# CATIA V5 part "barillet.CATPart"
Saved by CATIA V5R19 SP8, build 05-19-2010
Part number: barillet
Bounding box of the stored display mesh (mm): x -92.5 to 142.5, y -182.368 to 182.368, z -182.368 to 182.368
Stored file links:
  U:\Rendu_cfao_elguidj\barillet.CATPart
  U:\Rendu_cfao_elguidj\squelettecouronne.CATPart
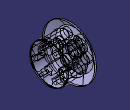
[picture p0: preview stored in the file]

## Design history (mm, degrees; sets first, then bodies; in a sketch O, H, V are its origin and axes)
Body1 (main body)
  DatumPoint1
  DatumCurve1
  Sketch1 on zx-plane, origin (0, 0, 0), H (-1, 0, 0), V (0, 0, 1)
    construction line L1 (114.6366, 0) -> (-102.6747, 0)
    point P1 (114.6366, 0)
    point P3 (-142.5, 128.5)
    line L2 (-142.5, 128.5) -> (-132.5, 128.5)
    line L3 (-132.5, 128.5) -> (-132.5, 132.5)
    line L4 (-132.5, 132.5) -> (0, 132.5)
    line L5 (0, 77.5) -> (-142.5, 77.5)
    line L6 (-142.5, 77.5) -> (-142.5, 128.5)
    point P9 (-142.5, 128.5)
    line L7 (0, 132.5) -> (0, 182.5)
    line L8 (0, 182.5) -> (12.5, 182.5)
    line L9 (12.5, 182.5) -> (42.5, 132.5)
    point P12 (42.5, 132.5)
    line L10 (42.5, 132.5) -> (42.5, 52.5)
    line L11 (42.5, 52.5) -> (44.5, 52.5)
    line L12 (44.5, 52.5) -> (44.5, 42.5)
    line L13 (44.5, 42.5) -> (89.5, 42.5)
    point P16 (89.5, 42.5)
    line L14 (0, 77.5) -> (0, 42.5)
    line L15 (0, 42.5) -> (22.5, 42.5)
    line L16 (22.5, 42.5) -> (22.5, 30)
    line L17 (22.5, 30) -> (85.1962, 30)
    line L18 (85.1962, 30) -> (92.5, 37.3038)
    point P21 (92.5, 37.3038)
    axis line L19 (89.5, 64.4527) -> (89.5, 13.1583)
    line L20 (92.5, 37.3038) -> (89.5, 42.5)
    distance L2 L4 = 4
    distance L8 L1 = 182.5
    length L7 = 50
    distance L10 L12 = 2
    distance L14 L6 = 142.5
    distance L14 L10 = 42.5
    length L8 = 12.5
    length L15 = 22.5
    length L16 = 12.5
    length L2 = 10
    distance L17 L1 = 30
    length L12 = 10
    distance L5 L1 = 77.5
    distance P21 L10 = 50
    angle L20 L13 = 60
    distance P21 L19 = 3
    angle L18 L17 = 45
    coincidence: P1 H, P9 L2, P3 L6, P3 P9, L14 V, L7 L14, L19 P16, L13 L15, P12 L4
    horizontal: L1 H, L2 H, L4 H, L5 H, L8 H, L11 H, L13 H, L15 H, L17 H
    vertical: L3 V, L6 V, L7 V, L10 V, L12 V, L14 V, L16 V, L19 V
  Shaft1: profile Sketch1, axis edge of DatumCurve1, angle 360
  DatumCurve2 to DatumCurve10
  Sketch2 on face of Shaft1 from Sketch1.L6, origin (142.5, 0, 0), H (0, 1, 0), V (0, 0, 1)
    circle A1 centre (0, 93.6948) radius 31.25
    reference projected circle E1 centre (0, 93.6948) radius 31.25 from edge of DatumCurve9
    circle A2 centre (81.1421, 46.8474) radius 31.25
    reference projected circle E2 centre (81.1421, 46.8474) radius 31.25 from edge of DatumCurve10
    circle A3 centre (81.1421, -46.8474) radius 31.25
    circle A4 centre (0, -93.6948) radius 31.25
    circle A5 centre (-81.1421, -46.8474) radius 31.25
    circle A6 centre (-81.1421, 46.8474) radius 31.25
    coincidence: A1 E1, A2 E2
    symmetry: A2 A3 H, A1 A4 H, A3 A5 V, A2 A6 V
  Pocket1: profile Sketch2, direction (-1, 0, 0), length 88
  DatumCurve11
  DatumCurve12
  Sketch3 on face of Shaft1 from Sketch1.L14, origin (0, 0, 0), H (0, 1, 0), V (0, 0, 1)
    circle A1 centre (46.8474, 81.1421) radius 31.25
    reference projected circle E1 centre (46.8474, 81.1421) radius 31.25 from edge of DatumCurve11
    circle A2 centre (93.6948, 0) radius 31.25
    reference projected circle E2 centre (93.6948, 0) radius 31.25 from edge of DatumCurve12
    circle A3 centre (-46.8474, 81.1421) radius 31.25
    circle A4 centre (-93.6948, 0) radius 31.25
    circle A5 centre (46.8474, -81.1421) radius 31.25
    circle A6 centre (-46.8474, -81.1421) radius 31.25
    coincidence: A1 E1, A2 E2
    symmetry: A1 A3 V, A2 A4 V, A1 A5 H, A3 A6 H
  Pocket2: profile Sketch3, direction (1, 0, 0), length 88, opposite side through (limit type 6)
  Sketch4 on face of Shaft1 from Sketch1.L6, origin (142.5, -55.155, 92.3968), H (0, 1, 0), V (0, 0, 1)
    point P1 (5.155, -5.7943)
    axis line L1 (165.2044, -283.0079) -> (-84.3122, 149.1674)
    reference projected point E1 (55.155, -92.3968) from vertex of Point1
    reference projected point E2 (55.155, -92.3968) from vertex of DatumPoint5
    angle L1 V = 30
    distance P1 E2 = 100
    coincidence: L1 E1, P1 L1
  Hole1: placed by Sketch4, at (142.5, -50, 86.6025) direction (-1, 0, 0), diameter 20, depth 46, V-bottom angle 120, threaded, thread diameter 22, thread depth 10, pitch 1
  DatumCurve13
  Plane1: stored without definition
  CircPattern1: of Hole1, instances 6, angular step 60, axis from edge of DatumCurve13
  DatumSurface1
  DatumSurface2
  Plane2: stored without definition
  Plane3: stored without definition
  Sketch5 on Plane1, origin (0, 0, -81.1421), H (1, 0, 0), V (0, 1, 0)
    line L1 (-21, -14.3474) -> (-19, -14.3474)
    line L2 (-19, -14.3474) -> (-19, -22.405)
    line L3 (-19, -22.405) -> (-21, -22.405)
    line L4 (-21, -22.405) -> (-21, -14.3474)
    reference intersected line E1 (-19, -14.3474) -> (-19, -19.8474) from face of DatumSurface1
    reference intersected line E2 (-21, -19.8474) -> (-21, -14.3474) from face of DatumSurface2
    reference intersected line E3 through (0, -46.8474) direction (-1, 0) from Plane2
    construction line L5 (-77.004, -46.8474) -> (-1.2892, -46.8474)
    reference intersected line E4 through (0, -46.8474) direction (-1, 0) from Plane3
    distance L1 E3 = 32.5
    horizontal: L1 H, L3 H, L5 H
    vertical: L2 V, L4 V
    coincidence: L2 E1, L4 E2, L5 E4
  Groove1: profile Sketch5, axis axis of face of Pocket2 from Sketch3.A6, angle 360
  DatumCurve14
  CircPattern2: of Groove1, instances 6, angular step 60, axis from edge of DatumCurve14
  DatumPoint2 to DatumPoint4
  Point1: stored without definition
  DatumPoint5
